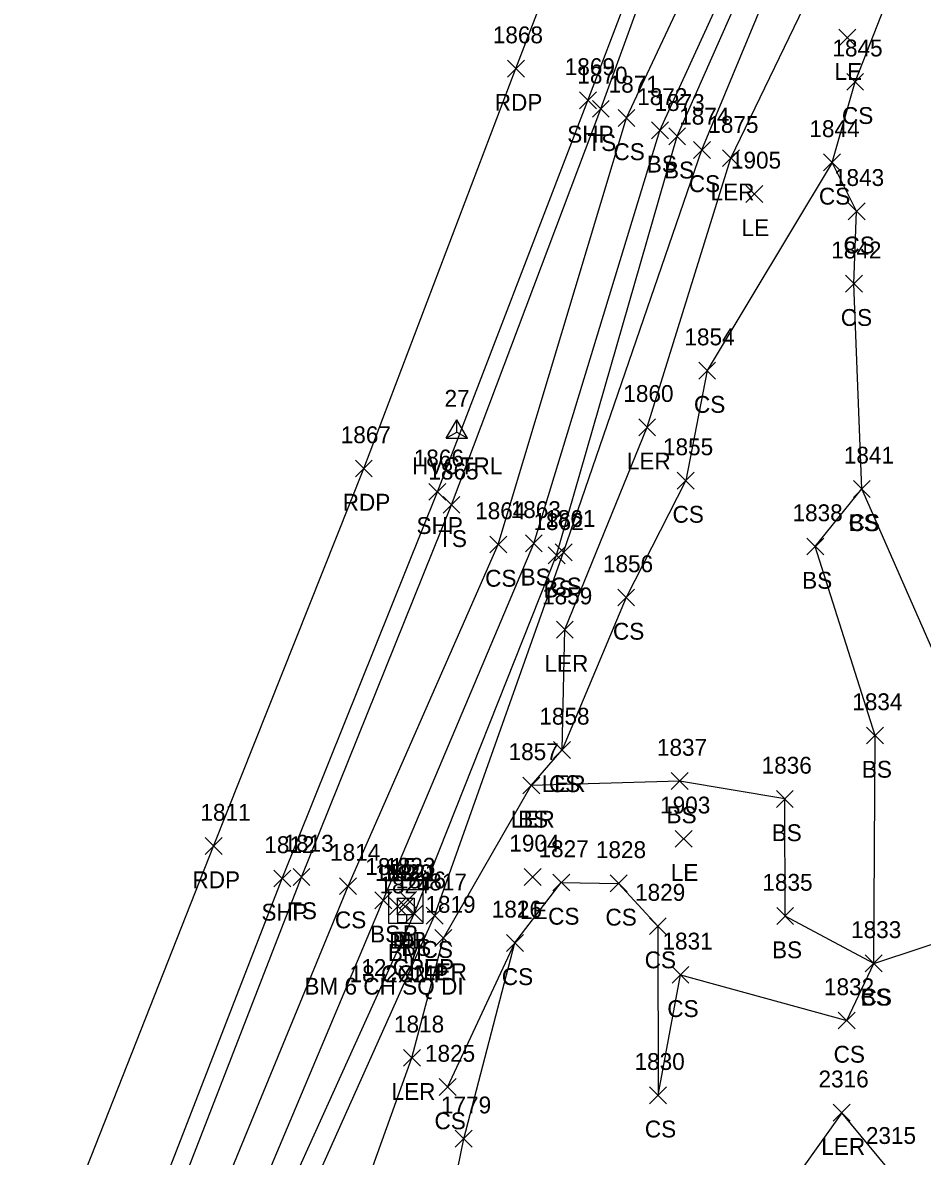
# Model space of a CAD drawing. Extents: x 1483143 to 1488182, y 802902 to 807581.
# Drawn here: x 1487817 to 1487923.7, y 806404.6 to 806539 of the extents above; entities that cross this region are included whole.
import ezdxf

# ---------------------------------------------------------------- set-up
doc = ezdxf.new("R2010")
doc.units = 0
for name, color, linetype in [('C_A', 7, 'Continuous'), ('C_C', 7, 'Continuous'), ('C_I', 7, 'Continuous'), ('CPBM', 7, 'Continuous'), ('CPSM', 7, 'Continuous'), ('D_A', 7, 'Continuous'), ('D_C', 7, 'Continuous'), ('D_I', 7, 'Continuous'), ('D_TIC', 7, 'Continuous'), ('DS', 7, 'Continuous'), ('L_A', 7, 'Continuous'), ('L_I', 7, 'Continuous'), ('L_TIC', 7, 'Continuous'), ('LARO', 7, 'Continuous'), ('LELB', 7, 'Continuous'), ('P_A', 7, 'Continuous'), ('P_I', 7, 'Continuous'), ('P_TIC', 7, 'Continuous'), ('PET', 7, 'Continuous'), ('PSP', 7, 'Continuous')]:
    doc.layers.add(name, color=color, linetype=linetype)

msp = doc.modelspace()

# ---------------------------------------------------------------- linework, layer by layer
at = {"layer": 'CPBM'}
for p, q in [((1487861.52, 806432.29), (1487861.52, 806433.29)), ((1487861.52, 806433.29), (1487862.52, 806433.29)), ((1487862.52, 806432.29), (1487861.52, 806432.29)), ((1487862.02, 806432.79), (1487862.02, 806432.79)), ((1487862.02, 806432.79), (1487862.02, 806432.79)), ((1487862.52, 806433.29), (1487862.52, 806432.29))]:
    msp.add_line(p, q, dxfattribs=at)
at = {"layer": 'CPSM'}
for p, q in [((1487867.25, 806489.75), (1487868.5, 806491.92)), ((1487869.75, 806489.75), (1487868.5, 806491.92)), ((1487868.5, 806490.47), (1487868.5, 806491.92)), ((1487867.25, 806489.75), (1487868.5, 806490.47)), ((1487868.5, 806490.47), (1487868.5, 806490.47)), ((1487868.5, 806490.47), (1487869.75, 806489.75)), ((1487867.25, 806489.75), (1487869.75, 806489.75))]:
    msp.add_line(p, q, dxfattribs=at)
at = {"layer": 'D_TIC'}
for points in [[(1487860.5, 806433.26), (1487862.5, 806435.26)], [(1487862.5, 806433.26), (1487860.5, 806435.26)], [(1487861.38, 806433.23), (1487863.38, 806435.23)], [(1487863.38, 806433.23), (1487861.38, 806435.23)], [(1487861.7, 806434), (1487863.7, 806436)], [(1487863.7, 806434), (1487861.7, 806436)]]:
    msp.add_lwpolyline(points, dxfattribs=at)
at = {"layer": 'DS'}
for p, q in [((1487860.45, 806436.23), (1487864.45, 806436.23)), ((1487860.45, 806432.23), (1487860.45, 806436.23)), ((1487864.45, 806436.23), (1487864.45, 806432.23)), ((1487861.45, 806433.23), (1487861.45, 806435.23)), ((1487861.45, 806435.23), (1487863.45, 806435.23)), ((1487863.45, 806435.23), (1487863.45, 806433.23)), ((1487862.45, 806434.23), (1487862.45, 806434.23)), ((1487862.45, 806434.23), (1487862.45, 806434.23)), ((1487864.45, 806432.23), (1487860.45, 806432.23)), ((1487863.45, 806433.23), (1487861.45, 806433.23))]:
    msp.add_line(p, q, dxfattribs=at)
at = {"layer": 'L_TIC'}
for points in [[(1487913.77, 806536.21), (1487915.77, 806538.21)], [(1487915.77, 806536.21), (1487913.77, 806538.21)], [(1487914.7, 806530.99), (1487916.7, 806532.99)], [(1487916.7, 806530.99), (1487914.7, 806532.99)], [(1487884.56, 806527.78), (1487886.56, 806529.78)], [(1487886.56, 806527.78), (1487884.56, 806529.78)], [(1487887.61, 806526.7), (1487889.61, 806528.7)], [(1487889.61, 806526.7), (1487887.61, 806528.7)], [(1487891.57, 806525.23), (1487893.57, 806527.23)], [(1487893.57, 806525.23), (1487891.57, 806527.23)], [(1487893.61, 806524.53), (1487895.61, 806526.53)], [(1487895.61, 806524.53), (1487893.61, 806526.53)], [(1487896.55, 806522.91), (1487898.55, 806524.91)], [(1487898.55, 806522.91), (1487896.55, 806524.91)], [(1487899.99, 806521.93), (1487901.99, 806523.93)], [(1487901.99, 806521.93), (1487899.99, 806523.93)], [(1487911.97, 806521.43), (1487913.97, 806523.43)], [(1487913.97, 806521.43), (1487911.97, 806523.43)], [(1487911.97, 806521.43), (1487913.97, 806523.43)], [(1487913.97, 806521.43), (1487911.97, 806523.43)], [(1487902.75, 806517.7), (1487904.75, 806519.7)], [(1487904.75, 806517.7), (1487902.75, 806519.7)], [(1487914.88, 806515.64), (1487916.88, 806517.64)], [(1487916.88, 806515.64), (1487914.88, 806517.64)], [(1487914.56, 806507.05), (1487916.56, 806509.05)], [(1487916.56, 806507.05), (1487914.56, 806509.05)], [(1487897.16, 806496.75), (1487899.16, 806498.75)], [(1487899.16, 806496.75), (1487897.16, 806498.75)], [(1487890.05, 806490.04), (1487892.05, 806492.04)], [(1487892.05, 806490.04), (1487890.05, 806492.04)], [(1487894.62, 806483.72), (1487896.62, 806485.72)], [(1487896.62, 806483.72), (1487894.62, 806485.72)], [(1487915.49, 806482.73), (1487917.49, 806484.73)], [(1487917.49, 806482.73), (1487915.49, 806484.73)], [(1487915.49, 806482.73), (1487917.49, 806484.73)], [(1487917.49, 806482.73), (1487915.49, 806484.73)], [(1487866.87, 806480.84), (1487868.87, 806482.84)], [(1487868.87, 806480.84), (1487866.87, 806482.84)], [(1487872.41, 806476.14), (1487874.41, 806478.14)], [(1487874.41, 806476.14), (1487872.41, 806478.14)], [(1487876.62, 806476.28), (1487878.62, 806478.28)], [(1487878.62, 806476.28), (1487876.62, 806478.28)], [(1487909.98, 806475.9), (1487911.98, 806477.9)], [(1487911.98, 806475.9), (1487909.98, 806477.9)], [(1487879.32, 806474.86), (1487881.32, 806476.86)], [(1487881.32, 806474.86), (1487879.32, 806476.86)], [(1487880.15, 806475.22), (1487882.15, 806477.22)], [(1487882.15, 806475.22), (1487880.15, 806477.22)], [(1487887.56, 806469.86), (1487889.56, 806471.86)], [(1487889.56, 806469.86), (1487887.56, 806471.86)], [(1487880.3, 806466.05), (1487882.3, 806468.05)], [(1487882.3, 806466.05), (1487880.3, 806468.05)], [(1487917.06, 806453.5), (1487919.06, 806455.5)], [(1487919.06, 806453.5), (1487917.06, 806455.5)], [(1487879.97, 806451.79), (1487881.97, 806453.79)], [(1487881.97, 806451.79), (1487879.97, 806453.79)], [(1487879.97, 806451.79), (1487881.97, 806453.79)], [(1487881.97, 806451.79), (1487879.97, 806453.79)], [(1487876.32, 806447.58), (1487878.32, 806449.58)], [(1487878.32, 806447.58), (1487876.32, 806449.58)], [(1487876.32, 806447.58), (1487878.32, 806449.58)], [(1487878.32, 806447.58), (1487876.32, 806449.58)], [(1487893.9, 806448.1), (1487895.9, 806450.1)], [(1487895.9, 806448.1), (1487893.9, 806450.1)], [(1487906.37, 806445.98), (1487908.37, 806447.98)], [(1487908.37, 806445.98), (1487906.37, 806447.98)], [(1487894.37, 806441.26), (1487896.37, 806443.26)], [(1487896.37, 806441.26), (1487894.37, 806443.26)], [(1487876.49, 806436.74), (1487878.49, 806438.74)], [(1487878.49, 806436.74), (1487876.49, 806438.74)], [(1487849.09, 806436.73), (1487851.09, 806438.73)], [(1487851.09, 806436.73), (1487849.09, 806438.73)], [(1487854.61, 806435.65), (1487856.61, 806437.65)], [(1487856.61, 806435.65), (1487854.61, 806437.65)], [(1487879.88, 806436.08), (1487881.88, 806438.08)], [(1487881.88, 806436.08), (1487879.88, 806438.08)], [(1487886.67, 806435.97), (1487888.67, 806437.97)], [(1487888.67, 806435.97), (1487886.67, 806437.97)], [(1487858.78, 806433.97), (1487860.78, 806435.97)], [(1487860.78, 806433.97), (1487858.78, 806435.97)], [(1487862.45, 806432.38), (1487864.45, 806434.38)], [(1487864.45, 806432.38), (1487862.45, 806434.38)], [(1487864.87, 806432.14), (1487866.87, 806434.14)], [(1487866.87, 806432.14), (1487864.87, 806434.14)], [(1487906.41, 806432.1), (1487908.41, 806434.1)], [(1487908.41, 806432.1), (1487906.41, 806434.1)], [(1487891.32, 806430.91), (1487893.32, 806432.91)], [(1487893.32, 806430.91), (1487891.32, 806432.91)], [(1487865.91, 806429.49), (1487867.91, 806431.49)], [(1487867.91, 806429.49), (1487865.91, 806431.49)], [(1487874.39, 806428.92), (1487876.39, 806430.92)], [(1487876.39, 806428.92), (1487874.39, 806430.92)], [(1487874.39, 806428.92), (1487876.39, 806430.92)], [(1487876.39, 806428.92), (1487874.39, 806430.92)], [(1487916.91, 806426.49), (1487918.91, 806428.49)], [(1487918.91, 806426.49), (1487916.91, 806428.49)], [(1487916.91, 806426.49), (1487918.91, 806428.49)], [(1487918.91, 806426.49), (1487916.91, 806428.49)], [(1487916.91, 806426.49), (1487918.91, 806428.49)], [(1487918.91, 806426.49), (1487916.91, 806428.49)], [(1487894, 806425.13), (1487896, 806427.13)], [(1487896, 806425.13), (1487894, 806427.13)], [(1487913.7, 806419.72), (1487915.7, 806421.72)], [(1487915.7, 806419.72), (1487913.7, 806421.72)], [(1487862.18, 806415.3), (1487864.18, 806417.3)], [(1487864.18, 806415.3), (1487862.18, 806417.3)], [(1487866.41, 806411.83), (1487868.41, 806413.83)], [(1487868.41, 806411.83), (1487866.41, 806413.83)], [(1487891.34, 806410.86), (1487893.34, 806412.86)], [(1487893.34, 806410.86), (1487891.34, 806412.86)], [(1487913.11, 806408.79), (1487915.11, 806410.79)], [(1487915.11, 806408.79), (1487913.11, 806410.79)], [(1487868.32, 806405.71), (1487870.32, 806407.71)], [(1487870.32, 806405.71), (1487868.32, 806407.71)]]:
    msp.add_lwpolyline(points, dxfattribs=at)
at = {"layer": 'LARO'}
for points in [[(1487852.63, 806386.9), (1487863.18, 806416.3), (1487866.91, 806430.49), (1487877.32, 806448.58), (1487880.97, 806452.79), (1487881.3, 806467.05), (1487891.05, 806491.04), (1487900.99, 806522.93), (1487913.1, 806548.05), (1487923.9, 806573.89), (1487931.07, 806589.41), (1487936.09, 806606.91), (1487943.25, 806629.75), (1487951.65, 806650.73), (1487955.83, 806665.17), (1487963.5, 806682.75)], [(1487919.67, 806403.09), (1487914.11, 806409.79), (1487906.78, 806399.47)]]:
    msp.add_lwpolyline(points, dxfattribs=at)
at = {"layer": 'LELB'}
for points in [[(1487827.52, 806379.6), (1487850.09, 806437.73), (1487867.87, 806481.84), (1487885.56, 806528.78), (1487894.77, 806554.11), (1487911.86, 806599.05), (1487925.11, 806635.03), (1487938.6, 806672.73), (1487954.13, 806715.2), (1487966.77, 806750.86), (1487982.82, 806798.37), (1488000.33, 806849.53), (1488013.76, 806891.57), (1488028.96, 806936.12), (1488043.22, 806981), (1488053.37, 807013.21), (1488065.46, 807054.1), (1488079.1, 807097.32), (1488091.92, 807141.06), (1488105.94, 807188.64)], [(1487831.61, 806378.23), (1487855.61, 806436.65), (1487873.41, 806477.14), (1487888.61, 806527.7), (1487900.29, 806552.66), (1487915.56, 806597.3), (1487929.53, 806633.53), (1487942.79, 806670.21), (1487957.7, 806713.57), (1487969.99, 806749.64), (1487987.61, 806796.79), (1487994.35, 806813.4), (1488006.31, 806847.85), (1488017.75, 806890.1), (1488033.51, 806934.67), (1488047.05, 806979.87), (1488058.1, 807011.89), (1488070.58, 807052.35), (1488082.44, 807096.83), (1488095.42, 807139.95), (1488114.02, 807186.94)], [(1487835.19, 806376.59), (1487859.78, 806434.97), (1487877.62, 806477.28), (1487892.57, 806526.23), (1487904.08, 806551.45), (1487919.68, 806595.15), (1487934.47, 806632.17), (1487947.69, 806668.31), (1487962.32, 806711.59), (1487973.69, 806748.32), (1487991.68, 806795.65), (1487997.75, 806809.49), (1487999.54, 806813.18), (1488009.67, 806846.56), (1488021.34, 806888.06), (1488037.67, 806932.78), (1488051.91, 806977.51), (1488062.67, 807010.29), (1488074.95, 807051.31), (1488088, 807095.72), (1488100.03, 807138.12), (1488122.67, 807183.2)], [(1487837.5, 806376), (1487863.45, 806433.38), (1487880.32, 806475.86), (1487894.61, 806525.53), (1487906.02, 806551.4), (1487922.48, 806594.15), (1487937, 806631.99), (1487949.11, 806668.02), (1487964.79, 806711), (1487978.4, 806746.47), (1487994.99, 806794.38), (1488000.35, 806808.82), (1488001.34, 806812.09), (1488011.23, 806845.63), (1488024.65, 806886.78), (1488040.19, 806931.5), (1488054.27, 806976.88), (1488065.68, 807009.57), (1488076.91, 807050.77), (1488090.18, 807095.37), (1488103.15, 807137.16), (1488127.49, 807179.54)], [(1487839.66, 806374.66), (1487865.87, 806433.14), (1487881.15, 806476.22), (1487897.55, 806523.91), (1487908.57, 806550.53), (1487926.89, 806591.97), (1487940.49, 806630.59), (1487952.54, 806666.3), (1487966.7, 806710.04), (1487981.74, 806745.96), (1487997.33, 806793.52), (1488011.64, 806832), (1488027.95, 806886.11), (1488041.92, 806927.39), (1488045.38, 806935.91), (1488056.2, 806975.87), (1488068.38, 807008.79), (1488080.46, 807050.29), (1488092.26, 807094.39), (1488105.79, 807135.26), (1488129.48, 807176.06)], [(1487866.81, 806394.33), (1487869.32, 806406.71), (1487875.39, 806429.92), (1487880.88, 806437.08), (1487887.67, 806436.97), (1487892.32, 806431.91), (1487892.34, 806411.86), (1487895, 806426.13), (1487914.7, 806420.72), (1487917.91, 806427.49), (1487929.02, 806431.15), (1487932.2, 806447.95), (1487916.49, 806483.73), (1487915.56, 806508.05), (1487915.88, 806516.64), (1487912.97, 806522.43), (1487915.7, 806531.99), (1487920.99, 806545.5)], [(1487912.97, 806522.43), (1487898.16, 806497.75), (1487895.62, 806484.72), (1487888.56, 806470.86), (1487880.97, 806452.79)], [(1487917.91, 806427.49), (1487918.06, 806454.5), (1487910.98, 806476.9), (1487916.49, 806483.73)], [(1487917.91, 806427.49), (1487907.41, 806433.1), (1487907.37, 806446.98), (1487894.9, 806449.1), (1487877.32, 806448.58)], [(1487867.41, 806412.83), (1487875.39, 806429.92)]]:
    msp.add_lwpolyline(points, dxfattribs=at)
at = {"layer": 'P_TIC'}
for points in [[(1487874.5, 806532.55), (1487876.5, 806534.55)], [(1487876.5, 806532.55), (1487874.5, 806534.55)], [(1487883.04, 806528.78), (1487885.04, 806530.78)], [(1487885.04, 806528.78), (1487883.04, 806530.78)], [(1487856.48, 806485.15), (1487858.48, 806487.15)], [(1487858.48, 806485.15), (1487856.48, 806487.15)], [(1487865.19, 806482.39), (1487867.19, 806484.39)], [(1487867.19, 806482.39), (1487865.19, 806484.39)], [(1487838.67, 806440.4), (1487840.67, 806442.4)], [(1487840.67, 806440.4), (1487838.67, 806442.4)], [(1487846.81, 806436.56), (1487848.81, 806438.56)], [(1487848.81, 806436.56), (1487846.81, 806438.56)]]:
    msp.add_lwpolyline(points, dxfattribs=at)
at = {"layer": 'PET'}
msp.add_lwpolyline([(1487817.05, 806384.04), (1487839.67, 806441.4), (1487857.48, 806486.15), (1487875.5, 806533.55), (1487884.95, 806558.16), (1487901.52, 806603.65), (1487914.56, 806639.6), (1487927.99, 806676.8), (1487943.06, 806720.01), (1487955.19, 806754.64), (1487971.37, 806801.63), (1487988.85, 806854.11), (1488002.85, 806896.07), (1488017.7, 806940.87), (1488031.56, 806984.9), (1488041.8, 807017.08), (1488054.37, 807058.25), (1488067.6, 807101.48), (1488080.81, 807144.82), (1488095.07, 807192.49)], dxfattribs=at)
at = {"layer": 'PSP'}
msp.add_lwpolyline([(1487825.55, 806380.21), (1487847.81, 806437.56), (1487866.19, 806483.39), (1487884.04, 806529.78), (1487893.44, 806554.46), (1487910.05, 806599.89), (1487923.16, 806635.65), (1487936.98, 806673.57), (1487951.99, 806715.79), (1487964.7, 806751.7), (1487980.81, 806798.97), (1487998.23, 806850.18), (1488012.19, 806892.24), (1488027.11, 806936.91), (1488041.21, 806981.53), (1488051.31, 807013.35), (1488064.14, 807054.93), (1488077.14, 807097.61), (1488090.36, 807141.77), (1488104.31, 807189.57)], dxfattribs=at)

# ---------------------------------------------------------------- texts
at = {"layer": 'C_A'}
for s, p in [('HVCTRL', (1487863.19, 806485.47)), ('BM', (1487860.33, 806427.79))]:
    msp.add_text(s, height=2, dxfattribs=at).set_placement(p)
at = {"layer": 'C_C'}
msp.add_text('BM 6 CH SQ DI', height=2, dxfattribs=at).set_placement((1487850.43, 806423.79))
at = {"layer": 'C_I'}
for s, p in [('27', (1487867.04, 806493.47)), ('1824', (1487859.33, 806435.79))]:
    msp.add_text(s, height=2, dxfattribs=at).set_placement(p)
at = {"layer": 'D_A'}
for s, p in [('DIB', (1487860.48, 806429.23)), ('P', (1487860.88, 806429.26)), ('DI', (1487861.51, 806429.23)), ('P', (1487862.08, 806430))]:
    msp.add_text(s, height=2, dxfattribs=at).set_placement(p)
at = {"layer": 'D_C'}
for s, p in [('12 CPEP', (1487857.17, 806426)), ('18 CGMP', (1487855.79, 806425.26)), ('2X2', (1487860.03, 806425.23))]:
    msp.add_text(s, height=2, dxfattribs=at).set_placement(p)
at = {"layer": 'D_I'}
for s, p in [('1822', (1487858.81, 806437.26)), ('1820', (1487859.67, 806437.23)), ('1823', (1487860.01, 806438)), ('1821', (1487860.25, 806437.23))]:
    msp.add_text(s, height=2, dxfattribs=at).set_placement(p)
at = {"layer": 'L_A'}
for s, p in [('LE', (1487913.26, 806532.21)), ('CS', (1487914.14, 806526.99)), ('TS', (1487883.97, 806523.78)), ('CS', (1487887.06, 806522.7)), ('BS', (1487891.01, 806521.23)), ('BS', (1487893.05, 806520.53)), ('CS', (1487895.99, 806518.91)), ('LER', (1487898.57, 806517.93)), ('CS', (1487911.41, 806517.43)), ('CS', (1487911.41, 806517.43)), ('LE', (1487902.24, 806513.7)), ('CS', (1487914.32, 806511.64)), ('CS', (1487914, 806503.05)), ('CS', (1487896.6, 806492.75)), ('LER', (1487888.64, 806486.04)), ('CS', (1487894.06, 806479.72)), ('CS', (1487914.93, 806478.73)), ('BS', (1487914.93, 806478.73)), ('TS', (1487866.28, 806476.84)), ('CS', (1487871.85, 806472.14)), ('BS', (1487876.06, 806472.28)), ('BS', (1487909.42, 806471.9)), ('BS', (1487878.76, 806470.86)), ('CS', (1487879.59, 806471.22)), ('CS', (1487887, 806465.86)), ('LER', (1487878.88, 806462.05)), ('BS', (1487916.5, 806449.5)), ('LER', (1487878.56, 806447.79)), ('CS', (1487879.42, 806447.79)), ('LER', (1487874.9, 806443.58)), ('BS', (1487875.76, 806443.58)), ('BS', (1487893.35, 806444.1)), ('BS', (1487905.81, 806441.98)), ('LE', (1487893.85, 806437.26)), ('TS', (1487848.5, 806432.73)), ('LE', (1487875.98, 806432.74)), ('CS', (1487854.05, 806431.65)), ('CS', (1487879.32, 806432.08)), ('CS', (1487886.11, 806431.97)), ('BS', (1487858.22, 806429.97)), ('BS', (1487861.89, 806428.38)), ('CS', (1487864.32, 806428.14)), ('BS', (1487905.85, 806428.1)), ('CS', (1487890.76, 806426.91)), ('LER', (1487864.49, 806425.49)), ('CS', (1487873.83, 806424.92)), ('CS', (1487873.83, 806424.92)), ('CS', (1487916.35, 806422.49)), ('BS', (1487916.35, 806422.49)), ('BS', (1487916.35, 806422.49)), ('CS', (1487893.44, 806421.13)), ('CS', (1487913.15, 806415.72)), ('LER', (1487860.76, 806411.3)), ('CS', (1487865.85, 806407.83)), ('CS', (1487890.78, 806406.86)), ('LER', (1487911.69, 806404.79))]:
    msp.add_text(s, height=2, dxfattribs=at).set_placement(p)
at = {"layer": 'L_I'}
for s, p in [('1845', (1487913.01, 806534.99)), ('1870', (1487882.78, 806531.78)), ('1871', (1487886.49, 806530.7)), ('1872', (1487889.87, 806529.23)), ('1873', (1487891.92, 806528.53)), ('1874', (1487894.85, 806526.91)), ('1875', (1487898.3, 806525.93)), ('1844', (1487910.28, 806525.43)), ('1844', (1487910.28, 806525.43)), ('1905', (1487900.98, 806521.7)), ('1843', (1487913.19, 806519.64)), ('1842', (1487912.87, 806511.05)), ('1854', (1487895.47, 806500.75)), ('1860', (1487888.23, 806494.04)), ('1855', (1487892.93, 806487.72)), ('1841', (1487914.36, 806486.73)), ('1841', (1487914.36, 806486.73)), ('1865', (1487865.13, 806484.84)), ('1864', (1487870.67, 806480.14)), ('1863', (1487874.88, 806480.28)), ('1838', (1487908.28, 806479.9)), ('1862', (1487877.58, 806478.86)), ('1861', (1487878.97, 806479.22)), ('1856', (1487885.81, 806473.86)), ('1859', (1487878.6, 806470.05)), ('1834', (1487915.36, 806457.5)), ('1858', (1487878.28, 806455.79)), ('1858', (1487878.28, 806455.79)), ('1857', (1487874.63, 806451.58)), ('1857', (1487874.63, 806451.58)), ('1837', (1487892.21, 806452.1)), ('1836', (1487904.62, 806449.98)), ('1903', (1487892.59, 806445.26)), ('1813', (1487847.96, 806440.73)), ('1814', (1487853.48, 806439.65)), ('1904', (1487874.72, 806440.74)), ('1827', (1487878.18, 806440.08)), ('1828', (1487884.98, 806439.97)), ('1815', (1487857.65, 806437.97)), ('1816', (1487861.26, 806436.38)), ('1817', (1487863.75, 806436.14)), ('1835', (1487904.71, 806436.1)), ('1829', (1487889.62, 806434.91)), ('1819', (1487864.77, 806433.49)), ('1826', (1487872.64, 806432.92)), ('1826', (1487872.64, 806432.92)), ('1833', (1487915.22, 806430.49)), ('1833', (1487915.22, 806430.49)), ('1833', (1487915.22, 806430.49)), ('1831', (1487892.87, 806429.13)), ('1832', (1487912.01, 806423.72)), ('1818', (1487861.05, 806419.3)), ('1825', (1487864.72, 806415.83)), ('1830', (1487889.56, 806414.86)), ('2316', (1487911.36, 806412.79)), ('1779', (1487866.62, 806409.71)), ('2315', (1487916.97, 806406.09))]:
    msp.add_text(s, height=2, dxfattribs=at).set_placement(p)
at = {"layer": 'P_A'}
for s, p in [('RDP', (1487872.99, 806528.55)), ('SHP', (1487881.58, 806524.78)), ('RDP', (1487854.97, 806481.15)), ('SHP', (1487863.72, 806478.39)), ('RDP', (1487837.16, 806436.4)), ('SHP', (1487845.34, 806432.56))]:
    msp.add_text(s, height=2, dxfattribs=at).set_placement(p)
at = {"layer": 'P_I'}
for s, p in [('1868', (1487872.76, 806536.55)), ('1869', (1487881.29, 806532.78)), ('1867', (1487854.74, 806489.15)), ('1866', (1487863.39, 806486.39)), ('1811', (1487838.11, 806444.4)), ('1812', (1487845.68, 806440.56))]:
    msp.add_text(s, height=2, dxfattribs=at).set_placement(p)

doc.saveas('drawing.dxf')
